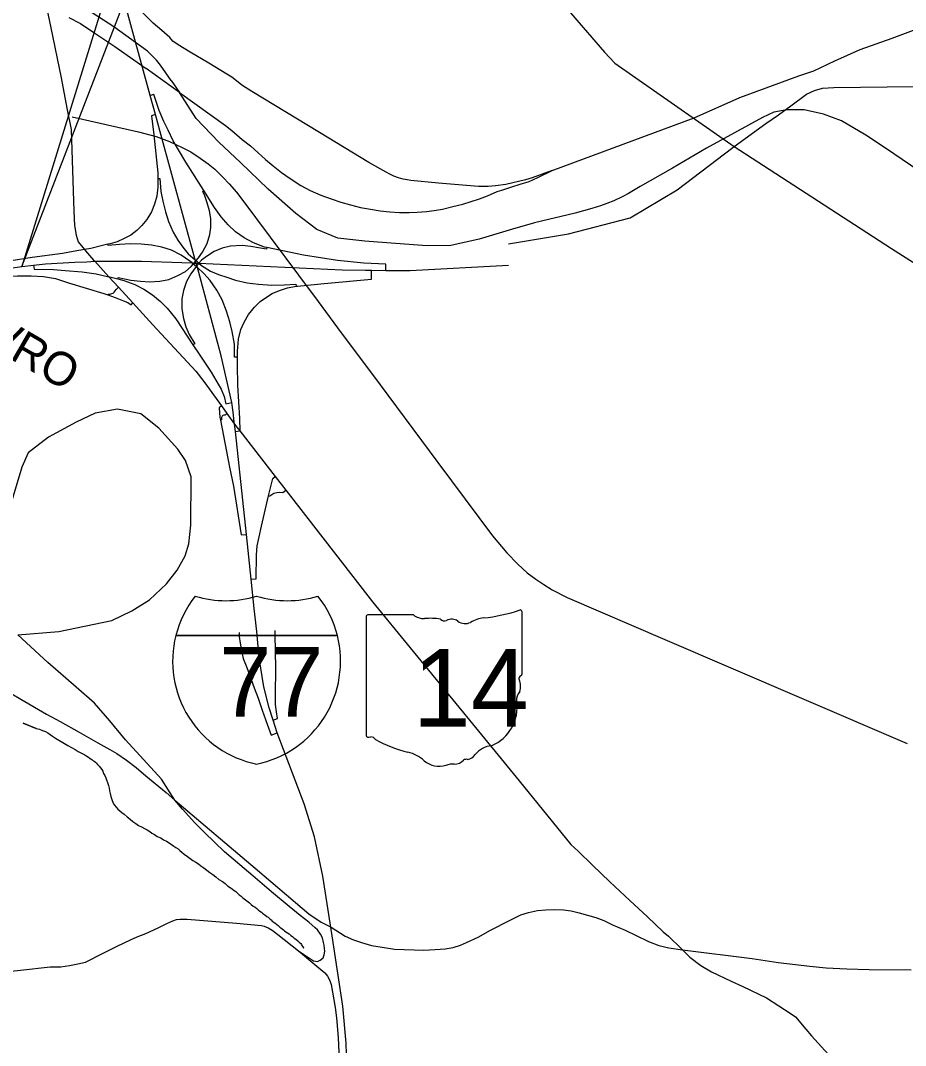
# Model space of a CAD drawing. Extents: x 0 to 96.2, y -27.5 to 31.3.
# Drawn here: x 47.422 to 48.919, y 16.212 to 17.946 of the extents above; entities that cross this region are included whole.
import ezdxf

# ---------------------------------------------------------------- set-up
doc = ezdxf.new("R2010")
doc.units = 0
for name, color, linetype in [('TB1', 7, 'Continuous'), ('TB_BORDER', 7, 'Continuous'), ('TB_DUAL_PROF', 7, 'Continuous'), ('TB_PP_50x10_GRID', 7, 'Continuous'), ('TB_PROF_20x5', 7, 'Continuous'), ('TB_PROF_20x5_GRID', 7, 'Continuous'), ('TB_PROF_30x10_GRID', 7, 'Continuous'), ('TB_PSDSOD', 7, 'Continuous'), ('TB_PSNSUM', 7, 'Continuous'), ('TB_SIGN_XS', 7, 'Continuous'), ('TB_SIGN_XS_GRID', 7, 'Continuous'), ('TB_SUPER_50x1', 7, 'Continuous')]:
    doc.layers.add(name, color=color, linetype=linetype)

msp = doc.modelspace()

# ---------------------------------------------------------------- linework, layer by layer
at = {"layer": 'TB1'}
msp.add_lwpolyline([(46.8522, 17.3284), (46.8555, 17.3299), (46.9267, 17.3616), (46.9897, 17.3916), (47.0195, 17.4057), (47.1509, 17.4678), (47.196, 17.481), (47.2332, 17.4919), (47.2987, 17.5086), (47.3491, 17.5196), (47.3717, 17.5227), (47.3835, 17.5244), (47.4236, 17.5299)], dxfattribs=at)
at = {"layer": 'TB_BORDER'}
for points in [[(47.4258, 16.7578), (47.448, 16.7485), (47.4258, 16.7578), (47.448, 16.7485), (47.4537, 16.7471), (47.459, 16.7452), (47.4636, 16.7434), (47.4678, 16.7412), (47.472, 16.7386), (47.4759, 16.7356), (47.4809, 16.7322), (47.4866, 16.7289), (47.4931, 16.7248), (47.5015, 16.7199), (47.5077, 16.7162), (47.5138, 16.7128), (47.5191, 16.7095), (47.5249, 16.7065), (47.5302, 16.7039), (47.5337, 16.7017), (47.5367, 16.6998), (47.5394, 16.698), (47.5421, 16.6961), (47.544, 16.6946), (47.5463, 16.6931), (47.5486, 16.6916), (47.5502, 16.6897), (47.5521, 16.6875), (47.5544, 16.6845), (47.5571, 16.6818), (47.559, 16.6792), (47.5606, 16.6762), (47.5622, 16.6724), (47.5641, 16.669), (47.5661, 16.6652), (47.5673, 16.6614), (47.5688, 16.6569), (47.5704, 16.6523), (47.5716, 16.6478), (47.5724, 16.6432), (47.5733, 16.6387), (47.5745, 16.6334), (47.5757, 16.63), (47.5768, 16.6266), (47.5776, 16.6236), (47.5788, 16.6209), (47.5804, 16.6186), (47.5865, 16.6119), (47.5896, 16.6093), (47.5931, 16.6063), (47.5969, 16.6033), (47.6023, 16.5988), (47.6069, 16.595), (47.6119, 16.5913), (47.6169, 16.5875), (47.6215, 16.5846), (47.6264, 16.582), (47.6314, 16.5794), (47.636, 16.5768), (47.6402, 16.5741), (47.644, 16.5715), (47.6482, 16.5693), (47.6529, 16.5659), (47.659, 16.5633), (47.6636, 16.5604), (47.6685, 16.5578), (47.6731, 16.5552), (47.677, 16.5525), (47.6808, 16.5496), (47.6846, 16.5473), (47.6881, 16.5451), (47.6911, 16.5421), (47.6946, 16.5391), (47.6984, 16.5361), (47.7042, 16.532), (47.7084, 16.5286), (47.713, 16.5252), (47.718, 16.5223), (47.7226, 16.5193), (47.7268, 16.5163), (47.7318, 16.5125), (47.7368, 16.5088), (47.7422, 16.5051), (47.7471, 16.5013), (47.7521, 16.4976), (47.7571, 16.4931), (47.7632, 16.4897), (47.7679, 16.4864), (47.7721, 16.4826), (47.7763, 16.4793), (47.7801, 16.4766), (47.7832, 16.4744), (47.7859, 16.4725), (47.7886, 16.4699), (47.7917, 16.4673), (47.7947, 16.4647), (47.7978, 16.462), (47.8089, 16.4534), (47.812, 16.4508), (47.8155, 16.4482), (47.8185, 16.446)], [(47.8185, 16.446), (47.8212, 16.4437), (47.8239, 16.4415), (47.8266, 16.4396), (47.8293, 16.4377), (47.8312, 16.4362), (47.8331, 16.4343), (47.835, 16.4332), (47.8385, 16.4302), (47.8404, 16.4291), (47.8439, 16.4261), (47.8458, 16.4246), (47.8473, 16.4227), (47.8492, 16.4216), (47.8519, 16.4198), (47.8546, 16.4175), (47.8577, 16.4153), (47.8604, 16.4126), (47.8623, 16.4111), (47.8642, 16.4093), (47.8665, 16.4078), (47.8684, 16.4063), (47.8707, 16.4044), (47.8734, 16.4029), (47.8761, 16.401), (47.8788, 16.3984), (47.8818, 16.3966), (47.8849, 16.3935), (47.8872, 16.3921), (47.8911, 16.3891), (47.893, 16.3872), (47.8957, 16.3849), (47.8968, 16.3831), (47.8976, 16.3812), (47.9007, 16.3774), (47.9011, 16.3774), (47.9011, 16.3778)]]:
    msp.add_lwpolyline(points, dxfattribs=at)
at = {"layer": 'TB_DUAL_PROF'}
for p, q in [((48.2702, 16.8411), (48.2702, 16.9458)), ((48.0065, 16.9374), (48.0065, 16.7373)), ((48.0864, 16.9408), (48.0091, 16.9408)), ((48.2702, 16.8411), (48.2702, 16.8411))]:
    msp.add_line(p, q, dxfattribs=at)
for centre, radius, start, end in [((48.1763, 17.2137), 0.2796, 275.8445, 288.9065), ((48.2673, 16.9462), 0.00294, 351.8621, 97.738), ((48.0096, 16.9378), 0.00305, 98.1301, 188.1301), ((48.1047, 16.9641), 0.0296, 231.6195, 271.1119), ((48.1146, 16.8285), 0.1064, 80.4867, 94.9883), ((48.1387, 16.9389), 0.00855, 219.7921, 297.1024), ((48.1513, 16.9157), 0.0178, 54.4667, 119.1411), ((48.1742, 16.9475), 0.0214, 233.8562, 294.8282), ((48.212, 16.8797), 0.0563, 97.3462, 120.7689), ((48.2671, 16.8407), 0.00314, 289.6038, 7.7341), ((48.2695, 16.8334), 0.00454, 107.944, 210.337), ((48.2406, 16.8202), 0.0273, 340.033, 23.6496), ((48.2807, 16.7973), 0.0198, 136.8065, 186.9296), ((48.1919, 16.784), 0.0699, 292.3089, 8.9858), ((48.0096, 16.7368), 0.00308, 171.9584, 258.3066), ((48.0101, 16.7573), 0.0235, 267.339, 280.6039), ((48.0149, 16.7257), 0.00848, 29.7484, 93.2717), ((48.1219, 16.9055), 0.2019, 240.4129, 257.1985), ((48.2214, 16.6811), 0.0383, 94.4031, 142.5768), ((48.0617, 16.6474), 0.0632, 47.1842, 75.836), ((48.1729, 16.7179), 0.0226, 282.8732, 323.2771), ((48.1301, 16.7247), 0.0401, 230.7004, 286.2918), ((48.1532, 16.6555), 0.0329, 85.6951, 111.2099), ((48.1561, 16.7097), 0.0214, 268.777, 315.5493), ((48.1755, 16.6904), 0.00601, 65.7517, 132.6484)]:
    msp.add_arc(centre, radius, start, end, dxfattribs=at)
at = {"layer": 'TB_PP_50x10_GRID'}
for points in [[(48.321, 17.6924), (48.5615, 17.7814), (48.6387, 17.8158), (48.7384, 17.8526), (48.7641, 17.8612), (48.7995, 17.8782), (48.8425, 17.897), (48.8963, 17.9164), (48.9462, 17.9349), (48.9581, 17.939), (48.9707, 17.9432), (48.9821, 17.9469), (48.9938, 17.9505), (49.0068, 17.9538), (49.0185, 17.957), (49.0407, 17.9615), (49.0549, 17.9643), (49.092, 17.9697), (49.1628, 17.9795), (49.2154, 17.9866), (49.2578, 17.9919)], [(47.6767, 17.845), (47.6582, 17.8705), (47.6514, 17.879), (47.6426, 17.8885), (47.6365, 17.8946), (47.5793, 17.9355), (47.5157, 17.9769)], [(47.5031, 17.9512), (47.5229, 17.9414), (47.5441, 17.9271), (47.5811, 17.9026), (47.6342, 17.8654)], [(48.321, 17.6924), (48.2875, 17.6803), (48.2761, 17.6766), (48.2428, 17.6689), (48.2252, 17.6665), (48.213, 17.6654), (48.1967, 17.6653), (48.1291, 17.6711), (48.082, 17.6758), (48.0759, 17.6765), (48.0689, 17.6777), (48.0611, 17.6799), (48.0534, 17.6828), (48.0466, 17.6861), (48.0402, 17.6896), (48.011, 17.7063), (47.9277, 17.7568), (47.8129, 17.8261), (47.7961, 17.8372), (47.7872, 17.8443), (47.7789, 17.8505), (47.7708, 17.8554), (47.7402, 17.8742), (47.7086, 17.8927), (47.6881, 17.9052), (47.6794, 17.9116), (47.6742, 17.9173), (47.6605, 17.9296), (47.6462, 17.9421), (47.6241, 17.9636)], [(47.6904, 17.8248), (47.6342, 17.8654)], [(47.6767, 17.845), (47.6904, 17.8248)], [(47.6904, 17.8248), (47.7683, 17.7689), (47.7794, 17.7602), (47.7967, 17.7448), (47.8106, 17.7344), (47.8236, 17.7224), (47.8364, 17.711), (47.8489, 17.7006), (47.8631, 17.6893), (47.878, 17.6789), (47.8958, 17.6674), (47.9118, 17.659), (47.9295, 17.651), (47.9474, 17.6444), (47.9635, 17.6392), (47.98, 17.6345), (47.9968, 17.6302), (48.0138, 17.6271), (48.0303, 17.6245), (48.0463, 17.6228), (48.0629, 17.6217), (48.0792, 17.6216), (48.0928, 17.6219), (48.1083, 17.623), (48.1217, 17.625), (48.1355, 17.6274), (48.1533, 17.6316), (48.1698, 17.6354), (48.198, 17.6448), (48.2116, 17.6498), (48.2281, 17.6568), (48.2361, 17.6592), (48.2528, 17.6649), (48.2671, 17.6694), (48.2822, 17.6739), (48.297, 17.6809), (48.321, 17.6924)], [(48.9418, 17.6919), (48.8855, 17.7301), (48.8522, 17.7524), (48.8108, 17.7768), (48.7806, 17.7878), (48.7476, 17.7952), (48.7182, 17.7952), (48.6962, 17.7915), (48.677, 17.7823), (48.5824, 17.7302), (48.525, 17.6967), (48.4704, 17.6655), (48.4504, 17.6539), (48.4394, 17.6482), (48.4257, 17.6415), (48.4138, 17.6368), (48.4028, 17.6328), (48.3882, 17.6284), (48.36, 17.6202), (48.2914, 17.6038), (48.254, 17.5933), (48.1977, 17.5762), (48.15, 17.5659), (48.1099, 17.5652), (48.0561, 17.5693), (48.0043, 17.5728), (47.9587, 17.5783), (47.9228, 17.5928), (47.8876, 17.6198), (47.8406, 17.6612), (47.7936, 17.7061), (47.757, 17.7407), (47.719, 17.7807), (47.6904, 17.8248)], [(47.5092, 17.7836), (47.5864, 17.7661), (47.6214, 17.7582), (47.6509, 17.7502), (47.6735, 17.7417), (47.695, 17.7314), (47.7095, 17.7239), (47.7256, 17.7134), (47.7393, 17.7039), (47.7502, 17.6946), (47.7642, 17.6814), (47.7747, 17.6701), (47.7872, 17.6559), (47.796, 17.6441), (47.8918, 17.5156), (47.9254, 17.4709), (47.9643, 17.4181), (48.0154, 17.3498), (48.1275, 17.1987), (48.2202, 17.0745), (48.2444, 17.0457), (48.2629, 17.0267), (48.2792, 17.0118), (48.2935, 17.001), (48.3072, 16.9919), (48.3215, 16.9831), (48.3465, 16.9703), (48.5119, 16.8989), (48.739, 16.8017), (48.922, 16.7229)], [(47.4172, 16.9068), (47.4862, 16.9124), (47.576, 16.9315), (47.6098, 16.9475), (47.64, 16.9661), (47.6686, 16.9932), (47.6869, 17.0165), (47.7, 17.0408), (47.7062, 17.0612), (47.7099, 17.0925), (47.7105, 17.1744), (47.701, 17.2018), (47.6879, 17.2211), (47.6555, 17.2565), (47.6251, 17.2809), (47.5856, 17.289), (47.5481, 17.2819), (47.5157, 17.2667), (47.4691, 17.2414), (47.4347, 17.215), (47.4236, 17.1907), (47.4074, 17.136), (47.4003, 17.0945), (47.4033, 17.056)], [(47.6826, 16.6275), (47.6602, 16.6629), (47.5995, 16.7294), (47.5726, 16.7615), (47.5467, 16.7916), (47.516, 16.8183), (47.4676, 16.8603), (47.4172, 16.9068)], [(47.3758, 16.8254), (47.4221, 16.798), (47.4657, 16.7729), (47.4886, 16.7605), (47.521, 16.7422), (47.5523, 16.7245), (47.5727, 16.7132), (47.5847, 16.7064), (47.6009, 16.695), (47.6173, 16.6827), (47.6337, 16.6687), (47.6678, 16.64), (47.6826, 16.6275)], [(47.8919, 16.3721), (47.9172, 16.3553), (47.9244, 16.3542), (47.9288, 16.3563), (47.9335, 16.3607), (47.9356, 16.3658), (47.9366, 16.3719), (47.9362, 16.3764), (47.9354, 16.3821), (47.9341, 16.3865), (47.9324, 16.3945), (47.9294, 16.4006), (47.9241, 16.4076), (47.9203, 16.4111), (47.9092, 16.4208), (47.895, 16.4324), (47.8759, 16.4474), (47.8461, 16.4719), (47.8146, 16.4991), (47.767, 16.5396), (47.7327, 16.5725), (47.7158, 16.5894), (47.7063, 16.6001), (47.6957, 16.6118), (47.6826, 16.6275)], [(47.6826, 16.6275), (47.8187, 16.5122), (47.8979, 16.4448), (47.9097, 16.4351), (47.9303, 16.421), (47.9472, 16.4122), (47.9709, 16.3969), (47.9852, 16.3911), (47.9987, 16.3862), (48.0157, 16.3815), (48.0335, 16.3783), (48.0547, 16.3754), (48.1039, 16.3734), (48.1233, 16.3746), (48.1402, 16.376), (48.1539, 16.3782), (48.1659, 16.3821), (48.1763, 16.3865), (48.1958, 16.3956), (48.2168, 16.4072), (48.2492, 16.4237), (48.2681, 16.433), (48.2813, 16.4374), (48.2962, 16.4404), (48.3106, 16.4418), (48.3256, 16.4424), (48.3405, 16.4417), (48.3535, 16.4402), (48.3667, 16.4369), (48.395, 16.4286), (48.4085, 16.4236), (48.4233, 16.4165), (48.4449, 16.4073), (48.4633, 16.3983), (48.4844, 16.3881), (48.5016, 16.3816), (48.5187, 16.3773), (48.5417, 16.374), (48.6597, 16.3591), (48.7036, 16.3526), (48.7572, 16.3463), (48.785, 16.3434), (48.8198, 16.3417), (48.8579, 16.3405), (48.9289, 16.3401)], [(47.3478, 16.3318), (47.4217, 16.3397), (47.472, 16.3451), (47.49, 16.3452), (47.5046, 16.3474), (47.5188, 16.3501), (47.5313, 16.3534), (47.5612, 16.3683), (47.585, 16.3803), (47.6075, 16.3912), (47.6192, 16.3961), (47.6338, 16.4017), (47.6547, 16.4115), (47.6693, 16.4184), (47.6794, 16.4229), (47.6857, 16.4251), (47.6917, 16.426), (47.6972, 16.4262), (47.7036, 16.426), (47.7871, 16.419), (47.8292, 16.4151), (47.8339, 16.4141), (47.8407, 16.4113), (47.8476, 16.4071), (47.8568, 16.4001), (47.8919, 16.3721)], [(47.8919, 16.3721), (47.9161, 16.3523), (47.9364, 16.3349), (47.9412, 16.3293), (47.9446, 16.3232), (47.9474, 16.3152), (47.9541, 16.2766), (47.9561, 16.2588), (47.959, 16.226), (47.9603, 16.2004), (47.9606, 16.1697)]]:
    msp.add_lwpolyline(points, dxfattribs=at)
at = {"layer": 'TB_PROF_20x5_GRID'}
for points in [[(48.0399, 17.5236), (48.04, 17.5342), (48.0028, 17.536), (47.9579, 17.5402), (47.9004, 17.5491), (47.8383, 17.5623), (47.8344, 17.5631), (47.8158, 17.5703), (47.8003, 17.5788), (47.7853, 17.589), (47.7727, 17.6009), (47.7611, 17.6139), (47.7498, 17.6302), (47.7319, 17.6585), (47.7015, 17.7066), (47.68, 17.7425), (47.6713, 17.7608), (47.6643, 17.7756), (47.6562, 17.7939), (47.6471, 17.8213), (47.641, 17.8197)], [(47.65, 17.7871), (47.6434, 17.7853), (47.6469, 17.753), (47.654, 17.6886), (47.654, 17.6792), (47.6539, 17.6641), (47.6521, 17.649), (47.6485, 17.6354), (47.6432, 17.6228), (47.6354, 17.6098), (47.6268, 17.5995), (47.6185, 17.5912), (47.6081, 17.5831), (47.5968, 17.5773), (47.5849, 17.5721), (47.5734, 17.5686), (47.5694, 17.5677), (47.5603, 17.5656), (47.5408, 17.5607), (47.5301, 17.5589), (47.5106, 17.5555), (47.4927, 17.5524), (47.4414, 17.5453), (47.4059, 17.54)], [(47.654, 17.6792), (47.6575, 17.6792), (47.6592, 17.6569), (47.6622, 17.6405), (47.667, 17.6224), (47.6722, 17.6063), (47.6797, 17.5884), (47.6877, 17.5748), (47.6961, 17.5628), (47.7055, 17.5518), (47.7172, 17.5414), (47.7187, 17.5401), (47.7235, 17.5358), (47.728, 17.5318), (47.7429, 17.522), (47.7566, 17.5164), (47.7705, 17.5119), (47.7854, 17.5071), (47.8052, 17.5025), (47.8241, 17.5003), (47.8468, 17.4983), (47.8677, 17.4994), (47.8874, 17.5), (47.888, 17.4967)], [(47.5863, 17.5091), (47.5869, 17.5115), (47.608, 17.5073), (47.6245, 17.5052), (47.6398, 17.5044), (47.6576, 17.5054), (47.6727, 17.5082), (47.6877, 17.5147), (47.7006, 17.5219), (47.7101, 17.5299), (47.7138, 17.5343), (47.7152, 17.536), (47.7179, 17.5391), (47.7187, 17.5401), (47.7229, 17.545), (47.7298, 17.5546), (47.7372, 17.5689), (47.7419, 17.5841), (47.7437, 17.5961), (47.7436, 17.6111), (47.7412, 17.6243), (47.7375, 17.6379), (47.7334, 17.6495), (47.7301, 17.6573), (47.7319, 17.6585)], [(47.7887, 17.377), (47.7836, 17.377), (47.7835, 17.3986), (47.7798, 17.42), (47.776, 17.4367), (47.7702, 17.4546), (47.7627, 17.4735), (47.7537, 17.4902), (47.7427, 17.5066), (47.7319, 17.5184), (47.7208, 17.5282), (47.7188, 17.53), (47.7138, 17.5343), (47.7118, 17.5361), (47.7081, 17.5394), (47.6932, 17.5494), (47.6771, 17.5575), (47.6609, 17.563), (47.6434, 17.5664), (47.6258, 17.5678), (47.6078, 17.5684), (47.5893, 17.5674), (47.5698, 17.5656), (47.5694, 17.5677)], [(47.8383, 17.5623), (47.8376, 17.5593), (47.8244, 17.5618), (47.8112, 17.5638), (47.7968, 17.5654), (47.7769, 17.5645), (47.7628, 17.561), (47.7494, 17.5553), (47.738, 17.5484), (47.7279, 17.5408), (47.7235, 17.5358), (47.7199, 17.5316), (47.7188, 17.53), (47.7096, 17.5176), (47.7026, 17.5047), (47.6972, 17.4898), (47.6948, 17.4753), (47.6947, 17.4586), (47.6972, 17.4423), (47.7011, 17.4282), (47.7072, 17.4149), (47.7163, 17.3994), (47.7134, 17.3975)], [(47.4436, 17.5326), (47.4447, 17.5258), (47.4774, 17.5249), (47.4971, 17.5236), (47.5259, 17.5212), (47.5497, 17.5178), (47.5711, 17.5129), (47.5726, 17.5125), (47.5863, 17.5091), (47.5966, 17.5066), (47.6151, 17.4998), (47.6304, 17.4916), (47.6449, 17.4821), (47.6585, 17.4712), (47.6696, 17.4595), (47.6844, 17.4416), (47.6951, 17.4252), (47.7134, 17.3975), (47.725, 17.38), (47.7443, 17.3512), (47.7562, 17.3312), (47.7613, 17.3225), (47.766, 17.3101), (47.769, 17.2978), (47.7792, 17.3002)], [(47.3835, 17.5244), (47.3853, 17.5132), (47.4167, 17.5145), (47.4396, 17.5141), (47.4607, 17.5132), (47.481, 17.5096), (47.5028, 17.5026), (47.5627, 17.4844), (47.5692, 17.4821), (47.5819, 17.4775), (47.5956, 17.4723), (47.6033, 17.469), (47.6086, 17.4653), (47.6118, 17.4685)], [(47.7852, 17.2512), (47.7926, 17.2522), (47.7935, 17.2523), (47.7925, 17.273), (47.7893, 17.3292), (47.7887, 17.3634), (47.7887, 17.377), (47.7888, 17.3871), (47.7905, 17.407), (47.7946, 17.4238), (47.7998, 17.4357), (47.8074, 17.449), (47.8173, 17.4616), (47.8272, 17.4707), (47.8364, 17.4774), (47.8473, 17.4842), (47.8598, 17.4898), (47.8733, 17.4939), (47.888, 17.4967), (47.8904, 17.4971), (47.9354, 17.5016), (48.0155, 17.5085), (48.0154, 17.5239)], [(47.5692, 17.4821), (47.5697, 17.4836), (47.573, 17.4836), (47.5761, 17.4842), (47.5782, 17.4851), (47.58, 17.4865), (47.5837, 17.491), (47.5876, 17.4949)], [(47.7616, 17.2942), (47.7576, 17.2911), (47.7589, 17.2744), (47.7597, 17.2704), (47.775, 17.1907), (47.7817, 17.1583), (47.795, 17.0759), (47.8038, 17.0768)], [(47.7709, 17.2813), (47.7676, 17.2787), (47.7656, 17.2786), (47.764, 17.278), (47.763, 17.2771), (47.7623, 17.2759), (47.7619, 17.2746), (47.7617, 17.2733), (47.7619, 17.271), (47.7597, 17.2704)], [(47.8119, 17.0011), (47.8204, 17.0018), (47.8211, 17.0421), (47.8223, 17.0576), (47.8252, 17.0728), (47.8293, 17.0908), (47.8414, 17.1424), (47.8483, 17.1713), (47.8527, 17.1748)], [(47.8414, 17.1424), (47.8432, 17.142), (47.8504, 17.1466), (47.8553, 17.148), (47.8605, 17.1483), (47.8656, 17.148), (47.8706, 17.1518)], [(47.7913, 16.9109), (47.7917, 16.904), (47.7932, 16.8926), (47.7953, 16.8801), (47.7986, 16.8672), (47.8043, 16.8515), (47.8172, 16.8175), (47.8237, 16.8), (47.8305, 16.7797), (47.8391, 16.756), (47.8457, 16.7374), (47.856, 16.7413)], [(47.8491, 16.7626), (47.8563, 16.7653), (47.8545, 16.7768), (47.8528, 16.7889), (47.8528, 16.8047), (47.8537, 16.8506), (47.8527, 16.9073), (47.8523, 16.9145)]]:
    msp.add_lwpolyline(points, dxfattribs=at)
at = {"layer": 'TB_PROF_30x10_GRID'}
msp.add_lwpolyline([(48.2474, 17.5683), (48.3491, 17.5853), (48.4532, 17.6125), (48.5326, 17.6597), (48.6268, 17.7316), (48.6293, 17.7334), (48.683, 17.7719), (48.704, 17.7869), (48.7249, 17.8018), (48.7518, 17.8217), (48.7652, 17.8277), (48.7785, 17.832), (48.7979, 17.8332), (49.0235, 17.8357)], dxfattribs=at)
at = {"layer": 'TB_PSDSOD'}
for points in [[(47.4517, 18.0363), (47.473, 17.9341)], [(47.473, 17.9341), (47.4906, 17.8492), (47.4999, 17.7981), (47.5071, 17.7618), (47.5116, 17.6237), (47.5132, 17.5994), (47.5155, 17.5831), (47.5191, 17.5718), (47.5301, 17.5589), (47.5317, 17.5569)], [(47.5317, 17.5569), (47.5453, 17.5411)], [(47.5453, 17.5411), (47.5472, 17.5389), (47.5711, 17.5129), (47.5876, 17.4949), (47.6118, 17.4685), (47.6457, 17.4317)], [(47.6457, 17.4317), (47.718, 17.353), (47.7318, 17.3353), (47.7616, 17.2942), (47.7709, 17.2813), (47.7836, 17.2636), (47.7899, 17.2556)], [(47.7899, 17.2556), (47.7926, 17.2522), (47.8527, 17.1748), (47.8706, 17.1518), (48.0174, 16.9629), (48.0811, 16.8849)], [(48.0811, 16.8849), (48.176, 16.7688)], [(48.176, 16.7688), (48.2651, 16.6598), (48.3529, 16.5521), (48.3651, 16.5409), (48.3896, 16.5173), (48.4188, 16.4891), (48.4529, 16.4576), (48.4824, 16.4298), (48.5092, 16.4047), (48.5181, 16.3969), (48.5398, 16.3757), (48.5541, 16.3618), (48.5729, 16.3477), (48.591, 16.3367), (48.6241, 16.3213), (48.6441, 16.3118)], [(48.6441, 16.3118), (48.6839, 16.2928), (48.7259, 16.2657), (48.7328, 16.2606), (48.7504, 16.2398)], [(48.7504, 16.2398), (48.7601, 16.2283), (48.8058, 16.1783), (48.8369, 16.1434), (48.8649, 16.1125), (48.8914, 16.0829), (48.9042, 16.0688), (48.9067, 16.0661), (48.9233, 16.0479), (48.9256, 16.0453)]]:
    msp.add_lwpolyline(points, dxfattribs=at)
at = {"layer": 'TB_PSNSUM'}
for points in [[(47.658, 17.7579), (47.65, 17.7871), (47.641, 17.8197), (47.5806, 18.0404), (47.5593, 18.1007), (47.5551, 18.1125), (47.5173, 18.1741), (47.4753, 18.2206), (47.4175, 18.2629)], [(47.7191, 17.5344), (47.7187, 17.5359), (47.7179, 17.5391), (47.7172, 17.5414), (47.658, 17.7579)], [(47.4236, 17.5299), (47.4436, 17.5326), (47.4636, 17.5347)], [(47.4636, 17.5347), (47.4638, 17.5347), (47.5137, 17.5372)], [(47.5137, 17.5372), (47.5338, 17.5382)], [(47.5338, 17.5382), (47.5472, 17.5389), (47.6264, 17.5389), (47.6944, 17.5367)], [(47.6944, 17.5367), (47.7118, 17.5361), (47.7152, 17.536), (47.7187, 17.5359), (47.7235, 17.5358), (47.9656, 17.5243), (48.0054, 17.5239)], [(47.727, 17.5052), (47.7208, 17.5282), (47.7199, 17.5316), (47.7191, 17.5344)], [(48.0054, 17.5239), (48.0154, 17.5239), (48.0399, 17.5236), (48.0808, 17.5232), (48.2476, 17.5324)], [(47.7812, 17.2838), (47.7792, 17.3002), (47.7612, 17.3788), (47.727, 17.5052)], [(47.7832, 17.2675), (47.7812, 17.2838)], [(47.7842, 17.2594), (47.7836, 17.2636), (47.7832, 17.2675)], [(47.8172, 16.9518), (47.8119, 17.0011), (47.8038, 17.0768), (47.7852, 17.2512), (47.7842, 17.2594)], [(47.9654, 15.8864), (47.9646, 15.9318), (47.9661, 15.9879), (47.9705, 16.0739), (47.9719, 16.1006), (47.9744, 16.1584), (47.9728, 16.2161), (47.9672, 16.2788), (47.9487, 16.3975), (47.9329, 16.4985), (47.9188, 16.5651), (47.9018, 16.6213), (47.856, 16.7413), (47.8491, 16.7626), (47.8424, 16.7832), (47.8333, 16.8191), (47.8256, 16.8683), (47.8214, 16.9124), (47.8172, 16.9518)]]:
    msp.add_lwpolyline(points, dxfattribs=at)
at = {"layer": 'TB_SIGN_XS'}
for points in [[(48.2359, 18.1025), (48.2387, 18.0916), (48.245, 18.0809), (48.2636, 18.0614), (48.2945, 18.0267), (48.4099, 17.8926), (48.4271, 17.8739), (48.4627, 17.8491)], [(48.4627, 17.8491), (48.6293, 17.7334), (48.6791, 17.7011)], [(48.6791, 17.7011), (48.8954, 17.5607), (49.0347, 17.4719), (49.1144, 17.4183), (49.2215, 17.3514), (49.2641, 17.3207), (49.2909, 17.3034), (49.3043, 17.2947)]]:
    msp.add_lwpolyline(points, dxfattribs=at)
at = {"layer": 'TB_SIGN_XS_GRID'}
for p, q in [((47.6845, 16.9059), (47.9578, 16.9059)), ((47.9578, 16.9059), (47.6845, 16.9059)), ((47.9578, 16.9059), (47.6845, 16.9059))]:
    msp.add_line(p, q, dxfattribs=at)
for centre, start, end in [((47.8566, 16.8624), 141.669, 165.8066), ((47.7692, 17.1423), 253.0091, 286.9909), ((47.873, 17.1423), 253.0091, 286.9909), ((47.7856, 16.8624), 14.1934, 38.331), ((47.8566, 16.8624), 165.8066, 258.463), ((47.7856, 16.8624), 281.537, 14.1934)]:
    msp.add_arc(centre, 0.1776, start, end, dxfattribs=at)
at = {"layer": 'TB_SUPER_50x1'}
msp.add_lwpolyline([(48.2252, 20.1257), (47.4236, 17.5299), (48.2252, 19.6035)], close=True, dxfattribs=at)

# ---------------------------------------------------------------- texts
at = {"layer": 'TB_DUAL_PROF'}
msp.add_text('14', height=0.13184, dxfattribs=at).set_placement((48.0855, 16.7514))
at = {"layer": 'TB_PROF_20x5'}
msp.add_text('CWRO', height=0.05663, rotation=330.0565, dxfattribs=at).set_placement((47.292, 17.438))
at = {"layer": 'TB_SIGN_XS_GRID'}
msp.add_text('77', height=0.11837, dxfattribs=at).set_placement((47.7579, 16.7683))

doc.saveas('drawing.dxf')
